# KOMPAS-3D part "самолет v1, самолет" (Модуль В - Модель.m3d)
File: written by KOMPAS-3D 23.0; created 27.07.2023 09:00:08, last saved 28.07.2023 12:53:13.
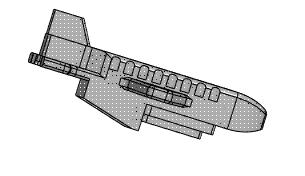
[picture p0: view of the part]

Document properties: Полное имя файла: C:\Users\safro\OneDrive\Рабочий стол\ИГ 2025\КЗ\Модуль В\Модуль В - Модель.m3d

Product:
- Part/product: самолет v1  | designation самолет
    Масса: 0.217105
    Форматы листов документа: A3

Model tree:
1. Операция без истории:1  (labels: самолет v1)
2. Фаска:1  (with: Операция без истории:1)
     Угол = 45; Длина 1 = 1; Длина 2 = 1
3. Эскиз:1  (with: Операция без истории:1)
4. Элемент выдавливания:1
     Расстояние 1 = 7
5. Эскиз:2  (with: Операция без истории:1)
6. Элемент выдавливания:2
     Расстояние 1 = 4
7. Скругление:1  (with: Элемент выдавливания:2, Элемент выдавливания:1)
     Радиус = 3
8. Скругление:2  (with: Элемент выдавливания:2, Элемент выдавливания:1)
     Радиус = 1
